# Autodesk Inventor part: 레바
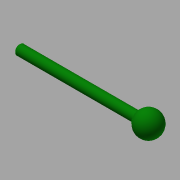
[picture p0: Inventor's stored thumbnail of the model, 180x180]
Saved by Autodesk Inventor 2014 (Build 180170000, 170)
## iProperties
Created: 2015-12
Part Number: 레바
Material: 스테인리스강
Document SubType Name: Modeling
Designer: mduedu
Density: 8.08 g/cm^3
Mass: 16.4908 g
Surface Area: 20.8622 cm^2
Volume: 2.04094 cm^3
Appearance: 진녹색
Author: mduedu
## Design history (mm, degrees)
sketch "스케치1"
  geometry: C1 r 3 at (0, 0); 1 further point
  constraints: 1 centre point, 1 coincident
  dimensions: "d0" = 6 diameter of C1
extrude "돌출1" new body sketch "스케치1" distance "d1" = 80; taper "d2" = 0 deg
sketch "스케치2"
  geometry: L1 (7.5, 0)-(-6, 0); L2 (-6, 4.5)-(-6, 0); A1 r 7.5 centre (0, 0) between (7.5, 0) and (-6, 4.5); 2 further points
  constraints: 4 end point, 2 coincident, 2 point on circle, 1 centre point, 1 horizontal, 1 perpendicular, 1 point on line
  dimensions: "d3" = 15 diameter of A1; "d10" = 6 distance from line of L2 point (0, 0)
revolve "회전1" sketch "스케치2" stored, may be unused: angle "d4" = 90 deg
chamfer "모따기1" distance "d7" = 0.5; stored, may be unused: second distance "d8" = 2, angle "d9" = 45 deg
fillet "모깎기2" dims "d11" = 0.3
node "솔리드1"
